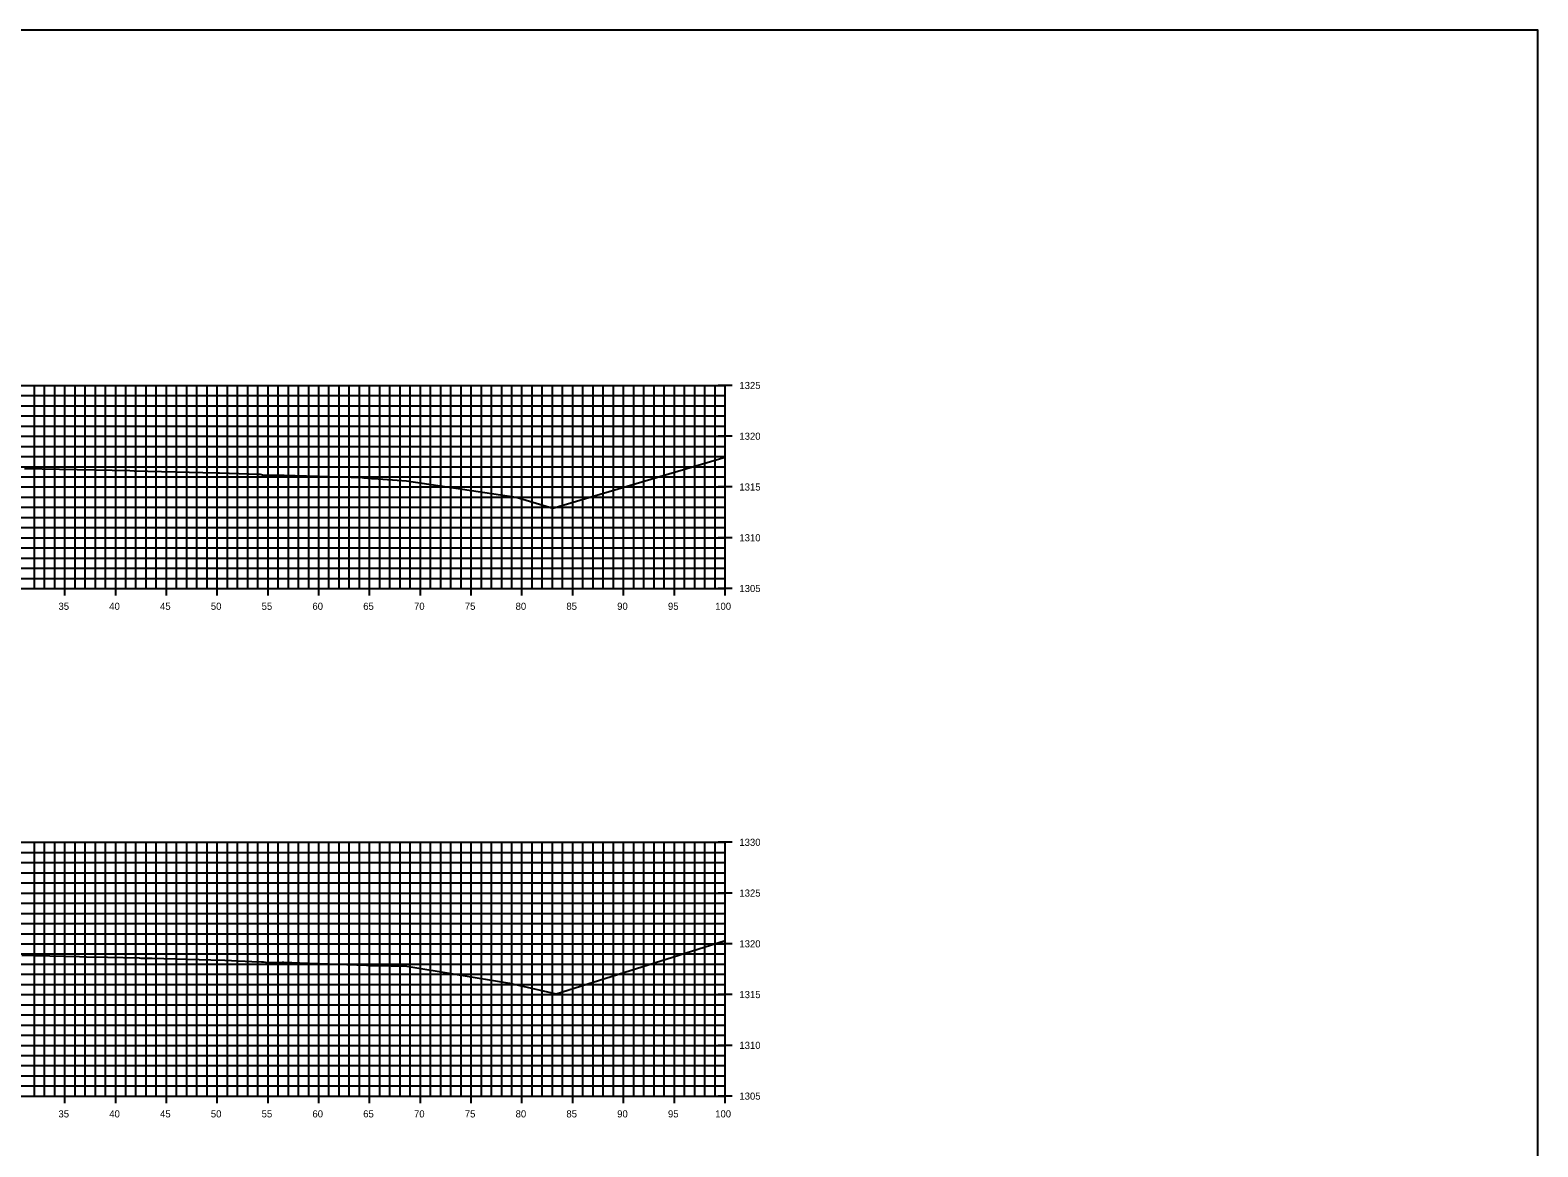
# Model space of a CAD drawing. Extents: x 674939 to 678919, y 750652 to 765176.
# Drawn here: x 678770.1 to 678918.5, y 753562.6 to 753672.6 of the extents above; entities that cross this region are included whole.
import ezdxf

# ---------------------------------------------------------------- set-up
doc = ezdxf.new("R2010")
doc.units = 0
for name, color, linetype in [('Level 10', 7, 'Continuous'), ('Level 20', 7, 'Continuous'), ('Level 4', 7, 'Continuous'), ('Level 8', 7, 'Continuous'), ('Level 9', 7, 'Continuous')]:
    doc.layers.add(name, color=color, linetype=linetype)

msp = doc.modelspace()

# ---------------------------------------------------------------- linework, layer by layer
at = {"layer": 'Level 10'}
for points in [[(678769.55, 753629.38), (678779.94, 753629.16), (678780.36, 753629.15), (678788.44, 753628.94), (678788.76, 753628.93), (678792.59, 753628.81), (678792.73, 753628.81), (678792.73, 753628.81), (678792.75, 753628.81), (678793.13, 753628.73), (678793.15, 753628.73), (678793.19, 753628.73), (678794.35, 753628.72), (678794.92, 753628.73), (678794.96, 753628.73), (678795.12, 753628.73), (678802.81, 753628.47), (678802.96, 753628.46), (678803.7, 753628.38), (678803.72, 753628.38), (678803.92, 753628.37), (678807.15, 753628.15), (678812.67, 753627.34), (678817.95, 753626.54), (678819.93, 753625.96), (678821.58, 753625.47), (678836.2, 753629.8), (678838.53, 753630.48)], [(678769.29, 753581.42), (678770.59, 753581.39), (678774.96, 753581.3), (678775.67, 753581.28), (678777.73, 753581.24), (678780.83, 753581.16), (678781.01, 753581.15), (678782.13, 753581.13), (678787.91, 753580.97), (678789.27, 753580.93), (678791.94, 753580.82), (678792.88, 753580.79), (678792.88, 753580.79), (678792.89, 753580.79), (678793.07, 753580.77), (678793.49, 753580.71), (678794.2, 753580.72), (678794.49, 753580.71), (678794.92, 753580.73), (678795.09, 753580.74), (678797.45, 753580.66), (678803.23, 753580.45), (678803.41, 753580.43), (678803.69, 753580.41), (678805.66, 753580.37), (678807.2, 753580.35), (678812.16, 753579.52), (678817.31, 753578.67), (678818.19, 753578.47), (678821.9, 753577.63), (678836.45, 753582.22), (678838.53, 753582.87)]]:
    msp.add_lwpolyline(points, dxfattribs=at)
at = {"layer": 'Level 20'}
for p, q in [((678638.53, 753637.55), (678838.53, 753637.55)), ((678770.53, 753617.55), (678770.53, 753637.55)), ((678771.53, 753617.55), (678771.53, 753637.55)), ((678772.53, 753617.55), (678772.53, 753637.55)), ((678773.53, 753617.55), (678773.53, 753637.55)), ((678774.53, 753617.55), (678774.53, 753637.55)), ((678775.53, 753617.55), (678775.53, 753637.55)), ((678776.53, 753617.55), (678776.53, 753637.55)), ((678777.53, 753617.55), (678777.53, 753637.55)), ((678778.53, 753617.55), (678778.53, 753637.55)), ((678779.53, 753617.55), (678779.53, 753637.55)), ((678780.53, 753617.55), (678780.53, 753637.55)), ((678781.53, 753617.55), (678781.53, 753637.55)), ((678782.53, 753617.55), (678782.53, 753637.55)), ((678783.53, 753617.55), (678783.53, 753637.55)), ((678784.53, 753617.55), (678784.53, 753637.55)), ((678785.53, 753617.55), (678785.53, 753637.55)), ((678786.53, 753617.55), (678786.53, 753637.55)), ((678787.53, 753617.55), (678787.53, 753637.55)), ((678788.53, 753617.55), (678788.53, 753637.55)), ((678789.53, 753617.55), (678789.53, 753637.55)), ((678790.53, 753617.55), (678790.53, 753637.55)), ((678791.53, 753617.55), (678791.53, 753637.55)), ((678792.53, 753617.55), (678792.53, 753637.55)), ((678793.53, 753617.55), (678793.53, 753637.55)), ((678794.53, 753617.55), (678794.53, 753637.55)), ((678795.53, 753617.55), (678795.53, 753637.55)), ((678796.53, 753617.55), (678796.53, 753637.55)), ((678797.53, 753617.55), (678797.53, 753637.55)), ((678798.53, 753617.55), (678798.53, 753637.55)), ((678799.53, 753617.55), (678799.53, 753637.55)), ((678800.53, 753617.55), (678800.53, 753637.55)), ((678801.53, 753617.55), (678801.53, 753637.55)), ((678802.53, 753617.55), (678802.53, 753637.55)), ((678803.53, 753617.55), (678803.53, 753637.55)), ((678804.53, 753617.55), (678804.53, 753637.55)), ((678805.53, 753617.55), (678805.53, 753637.55)), ((678806.53, 753617.55), (678806.53, 753637.55)), ((678807.53, 753617.55), (678807.53, 753637.55)), ((678808.53, 753617.55), (678808.53, 753637.55)), ((678809.53, 753617.55), (678809.53, 753637.55)), ((678810.53, 753617.55), (678810.53, 753637.55)), ((678811.53, 753617.55), (678811.53, 753637.55)), ((678812.53, 753617.55), (678812.53, 753637.55)), ((678813.53, 753617.55), (678813.53, 753637.55)), ((678814.53, 753617.55), (678814.53, 753637.55)), ((678815.53, 753617.55), (678815.53, 753637.55)), ((678816.53, 753617.55), (678816.53, 753637.55)), ((678817.53, 753617.55), (678817.53, 753637.55)), ((678818.53, 753617.55), (678818.53, 753637.55)), ((678819.53, 753617.55), (678819.53, 753637.55)), ((678820.53, 753617.55), (678820.53, 753637.55)), ((678821.53, 753617.55), (678821.53, 753637.55)), ((678822.53, 753617.55), (678822.53, 753637.55)), ((678823.53, 753617.55), (678823.53, 753637.55)), ((678824.53, 753617.55), (678824.53, 753637.55)), ((678825.53, 753617.55), (678825.53, 753637.55)), ((678826.53, 753617.55), (678826.53, 753637.55)), ((678827.53, 753617.55), (678827.53, 753637.55)), ((678828.53, 753617.55), (678828.53, 753637.55)), ((678829.53, 753617.55), (678829.53, 753637.55)), ((678830.53, 753617.55), (678830.53, 753637.55)), ((678831.53, 753617.55), (678831.53, 753637.55)), ((678832.53, 753617.55), (678832.53, 753637.55)), ((678833.53, 753617.55), (678833.53, 753637.55)), ((678834.53, 753617.55), (678834.53, 753637.55)), ((678835.53, 753617.55), (678835.53, 753637.55)), ((678836.53, 753617.55), (678836.53, 753637.55)), ((678837.53, 753617.55), (678837.53, 753637.55)), ((678838.53, 753617.55), (678838.53, 753637.55)), ((678638.53, 753636.55), (678838.53, 753636.55)), ((678638.53, 753635.55), (678838.53, 753635.55)), ((678638.53, 753634.55), (678838.53, 753634.55)), ((678638.53, 753633.55), (678838.53, 753633.55)), ((678638.53, 753632.55), (678838.53, 753632.55)), ((678638.53, 753631.55), (678838.53, 753631.55)), ((678638.53, 753630.55), (678838.53, 753630.55)), ((678638.53, 753629.55), (678838.53, 753629.55)), ((678638.53, 753628.55), (678838.53, 753628.55)), ((678638.53, 753627.55), (678838.53, 753627.55)), ((678638.53, 753626.55), (678838.53, 753626.55)), ((678638.53, 753625.55), (678838.53, 753625.55)), ((678638.53, 753624.55), (678838.53, 753624.55)), ((678638.53, 753623.55), (678838.53, 753623.55)), ((678638.53, 753622.55), (678838.53, 753622.55)), ((678638.53, 753621.55), (678838.53, 753621.55)), ((678638.53, 753620.55), (678838.53, 753620.55)), ((678638.53, 753619.55), (678838.53, 753619.55)), ((678638.53, 753618.55), (678838.53, 753618.55)), ((678638.53, 753617.55), (678838.53, 753617.55)), ((678638.53, 753592.55), (678838.53, 753592.55)), ((678770.53, 753567.55), (678770.53, 753592.55)), ((678771.53, 753567.55), (678771.53, 753592.55)), ((678772.53, 753567.55), (678772.53, 753592.55)), ((678773.53, 753567.55), (678773.53, 753592.55)), ((678774.53, 753567.55), (678774.53, 753592.55)), ((678775.53, 753567.55), (678775.53, 753592.55)), ((678776.53, 753567.55), (678776.53, 753592.55)), ((678777.53, 753567.55), (678777.53, 753592.55)), ((678778.53, 753567.55), (678778.53, 753592.55)), ((678779.53, 753567.55), (678779.53, 753592.55)), ((678780.53, 753567.55), (678780.53, 753592.55)), ((678781.53, 753567.55), (678781.53, 753592.55)), ((678782.53, 753567.55), (678782.53, 753592.55)), ((678783.53, 753567.55), (678783.53, 753592.55)), ((678784.53, 753567.55), (678784.53, 753592.55)), ((678785.53, 753567.55), (678785.53, 753592.55)), ((678786.53, 753567.55), (678786.53, 753592.55)), ((678787.53, 753567.55), (678787.53, 753592.55)), ((678788.53, 753567.55), (678788.53, 753592.55)), ((678789.53, 753567.55), (678789.53, 753592.55)), ((678790.53, 753567.55), (678790.53, 753592.55)), ((678791.53, 753567.55), (678791.53, 753592.55)), ((678792.53, 753567.55), (678792.53, 753592.55)), ((678793.53, 753567.55), (678793.53, 753592.55)), ((678794.53, 753567.55), (678794.53, 753592.55)), ((678795.53, 753567.55), (678795.53, 753592.55)), ((678796.53, 753567.55), (678796.53, 753592.55)), ((678797.53, 753567.55), (678797.53, 753592.55)), ((678798.53, 753567.55), (678798.53, 753592.55)), ((678799.53, 753567.55), (678799.53, 753592.55)), ((678800.53, 753567.55), (678800.53, 753592.55)), ((678801.53, 753567.55), (678801.53, 753592.55)), ((678802.53, 753567.55), (678802.53, 753592.55)), ((678803.53, 753567.55), (678803.53, 753592.55)), ((678804.53, 753567.55), (678804.53, 753592.55)), ((678805.53, 753567.55), (678805.53, 753592.55)), ((678806.53, 753567.55), (678806.53, 753592.55)), ((678807.53, 753567.55), (678807.53, 753592.55)), ((678808.53, 753567.55), (678808.53, 753592.55)), ((678809.53, 753567.55), (678809.53, 753592.55)), ((678810.53, 753567.55), (678810.53, 753592.55)), ((678811.53, 753567.55), (678811.53, 753592.55)), ((678812.53, 753567.55), (678812.53, 753592.55)), ((678813.53, 753567.55), (678813.53, 753592.55)), ((678814.53, 753567.55), (678814.53, 753592.55)), ((678815.53, 753567.55), (678815.53, 753592.55)), ((678816.53, 753567.55), (678816.53, 753592.55)), ((678817.53, 753567.55), (678817.53, 753592.55)), ((678818.53, 753567.55), (678818.53, 753592.55)), ((678819.53, 753567.55), (678819.53, 753592.55)), ((678820.53, 753567.55), (678820.53, 753592.55)), ((678821.53, 753567.55), (678821.53, 753592.55)), ((678822.53, 753567.55), (678822.53, 753592.55)), ((678823.53, 753567.55), (678823.53, 753592.55)), ((678824.53, 753567.55), (678824.53, 753592.55)), ((678825.53, 753567.55), (678825.53, 753592.55)), ((678826.53, 753567.55), (678826.53, 753592.55)), ((678827.53, 753567.55), (678827.53, 753592.55)), ((678828.53, 753567.55), (678828.53, 753592.55)), ((678829.53, 753567.55), (678829.53, 753592.55)), ((678830.53, 753567.55), (678830.53, 753592.55)), ((678831.53, 753567.55), (678831.53, 753592.55)), ((678832.53, 753567.55), (678832.53, 753592.55)), ((678833.53, 753567.55), (678833.53, 753592.55)), ((678834.53, 753567.55), (678834.53, 753592.55)), ((678835.53, 753567.55), (678835.53, 753592.55)), ((678836.53, 753567.55), (678836.53, 753592.55)), ((678837.53, 753567.55), (678837.53, 753592.55)), ((678838.53, 753567.55), (678838.53, 753592.55)), ((678638.53, 753591.55), (678838.53, 753591.55)), ((678638.53, 753590.55), (678838.53, 753590.55)), ((678638.53, 753589.55), (678838.53, 753589.55)), ((678638.53, 753588.55), (678838.53, 753588.55)), ((678638.53, 753587.55), (678838.53, 753587.55)), ((678638.53, 753586.55), (678838.53, 753586.55)), ((678638.53, 753585.55), (678838.53, 753585.55)), ((678638.53, 753584.55), (678838.53, 753584.55)), ((678638.53, 753583.55), (678838.53, 753583.55)), ((678638.53, 753582.55), (678838.53, 753582.55)), ((678638.53, 753581.55), (678838.53, 753581.55)), ((678638.53, 753580.55), (678838.53, 753580.55)), ((678638.53, 753579.55), (678838.53, 753579.55)), ((678638.53, 753578.55), (678838.53, 753578.55)), ((678638.53, 753577.55), (678838.53, 753577.55)), ((678638.53, 753576.55), (678838.53, 753576.55)), ((678638.53, 753575.55), (678838.53, 753575.55)), ((678638.53, 753574.55), (678838.53, 753574.55)), ((678638.53, 753573.55), (678838.53, 753573.55)), ((678638.53, 753572.55), (678838.53, 753572.55)), ((678638.53, 753571.55), (678838.53, 753571.55)), ((678638.53, 753570.55), (678838.53, 753570.55)), ((678638.53, 753569.55), (678838.53, 753569.55)), ((678638.53, 753568.55), (678838.53, 753568.55)), ((678638.53, 753567.55), (678838.53, 753567.55))]:
    msp.add_line(p, q, dxfattribs=at)
at = {"layer": 'Level 4'}
msp.add_lwpolyline([(678578.53, 753452.55), (678918.53, 753452.55), (678918.53, 753672.55), (678578.53, 753672.55)], close=True, dxfattribs=at)
at = {"layer": 'Level 8'}
for p, q in [((678839.23, 753637.55), (678837.83, 753637.55)), ((678838.53, 753617.55), (678838.53, 753637.55)), ((678839.23, 753632.55), (678837.83, 753632.55)), ((678839.23, 753627.55), (678837.83, 753627.55)), ((678839.23, 753622.55), (678837.83, 753622.55)), ((678638.53, 753617.55), (678838.53, 753617.55)), ((678773.53, 753616.85), (678773.53, 753618.25)), ((678778.53, 753616.85), (678778.53, 753618.25)), ((678783.53, 753616.85), (678783.53, 753618.25)), ((678788.53, 753616.85), (678788.53, 753618.25)), ((678793.53, 753616.85), (678793.53, 753618.25)), ((678798.53, 753616.85), (678798.53, 753618.25)), ((678803.53, 753616.85), (678803.53, 753618.25)), ((678808.53, 753616.85), (678808.53, 753618.25)), ((678813.53, 753616.85), (678813.53, 753618.25)), ((678818.53, 753616.85), (678818.53, 753618.25)), ((678823.53, 753616.85), (678823.53, 753618.25)), ((678828.53, 753616.85), (678828.53, 753618.25)), ((678833.53, 753616.85), (678833.53, 753618.25)), ((678839.23, 753617.55), (678837.83, 753617.55)), ((678838.53, 753616.85), (678838.53, 753618.25)), ((678839.23, 753592.55), (678837.83, 753592.55)), ((678838.53, 753567.55), (678838.53, 753592.55)), ((678839.23, 753587.55), (678837.83, 753587.55)), ((678839.23, 753582.55), (678837.83, 753582.55)), ((678839.23, 753577.55), (678837.83, 753577.55)), ((678839.23, 753572.55), (678837.83, 753572.55)), ((678638.53, 753567.55), (678838.53, 753567.55)), ((678773.53, 753566.85), (678773.53, 753568.25)), ((678778.53, 753566.85), (678778.53, 753568.25)), ((678783.53, 753566.85), (678783.53, 753568.25)), ((678788.53, 753566.85), (678788.53, 753568.25)), ((678793.53, 753566.85), (678793.53, 753568.25)), ((678798.53, 753566.85), (678798.53, 753568.25)), ((678803.53, 753566.85), (678803.53, 753568.25)), ((678808.53, 753566.85), (678808.53, 753568.25)), ((678813.53, 753566.85), (678813.53, 753568.25)), ((678818.53, 753566.85), (678818.53, 753568.25)), ((678823.53, 753566.85), (678823.53, 753568.25)), ((678828.53, 753566.85), (678828.53, 753568.25)), ((678833.53, 753566.85), (678833.53, 753568.25)), ((678839.23, 753567.55), (678837.83, 753567.55)), ((678838.53, 753566.85), (678838.53, 753568.25))]:
    msp.add_line(p, q, dxfattribs=at)

# ---------------------------------------------------------------- texts
at = {"layer": 'Level 9'}
for s, p in [('1325', (678839.93, 753637.2)), ('1320', (678839.93, 753632.2)), ('1315', (678839.93, 753627.2)), ('1310', (678839.93, 753622.2)), ('1305', (678839.93, 753617.2)), ('35', (678772.9, 753615.45)), ('40', (678777.9, 753615.45)), ('45', (678782.9, 753615.45)), ('50', (678787.9, 753615.45)), ('55', (678792.9, 753615.45)), ('60', (678797.9, 753615.45)), ('65', (678802.9, 753615.45)), ('70', (678807.9, 753615.45)), ('75', (678812.9, 753615.45)), ('80', (678817.9, 753615.45)), ('85', (678822.9, 753615.45)), ('90', (678827.9, 753615.45)), ('95', (678832.9, 753615.45)), ('100', (678837.55, 753615.45)), ('1330', (678839.93, 753592.2)), ('1325', (678839.93, 753587.2)), ('1320', (678839.93, 753582.2)), ('1315', (678839.93, 753577.2)), ('1310', (678839.93, 753572.2)), ('1305', (678839.93, 753567.2)), ('35', (678772.9, 753565.45)), ('40', (678777.9, 753565.45)), ('45', (678782.9, 753565.45)), ('50', (678787.9, 753565.45)), ('55', (678792.9, 753565.45)), ('60', (678797.9, 753565.45)), ('65', (678802.9, 753565.45)), ('70', (678807.9, 753565.45)), ('75', (678812.9, 753565.45)), ('80', (678817.9, 753565.45)), ('85', (678822.9, 753565.45)), ('90', (678827.9, 753565.45)), ('95', (678832.9, 753565.45)), ('100', (678837.55, 753565.45))]:
    msp.add_text(s, height=0.7, dxfattribs=at).set_placement(p)

doc.saveas('drawing.dxf')
